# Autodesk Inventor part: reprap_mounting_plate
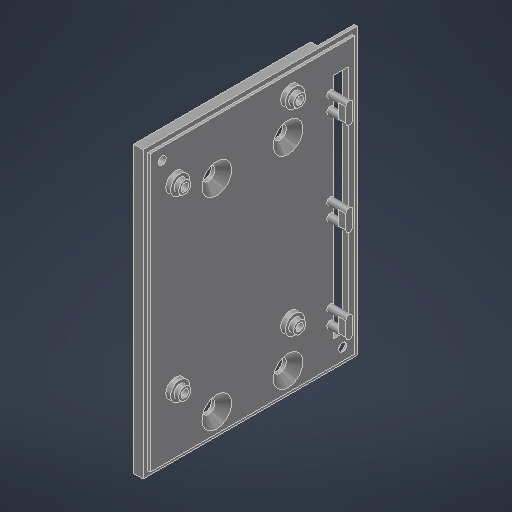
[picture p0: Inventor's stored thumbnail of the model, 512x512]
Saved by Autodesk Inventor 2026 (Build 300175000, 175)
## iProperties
Created: 2025-04
Part Number: reprap_mounting_plate
Material: 1.0037 S235JR
Document SubType Name: Modeling
Designer: BennF
Density: 7.85 g/cm^3
Appearance: Stahl
Author: BennF
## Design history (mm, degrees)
sketch "Sketch2"
  geometry: L1 (-45, 60)-(45, 60); L2 (45, 60)-(45, -60); L3 (45, -60)-(-45, -60); L4 (-45, -60)-(-45, 60); 3 further points
  constraints: 8 end point, 2 midpoint, 2 parallel, 1 horizontal, 1 horizontal alignment, 1 perpendicular, 1 vertical alignment
  dimensions: "d0" = 90 distance of L1.start L1.end; "d1" = 120 distance of L3.end L1.start
extrude "Extrusion1" new body sketch "Sketch2" distance "d2" = 5; taper "d3" = 0 deg
sketch "Sketch3"
  geometry: L1 (-60, 45)-(60, 45) reference; L2 (60, 45)-(-60, 45); L3 (-60, 45)-(-60, 29.5); L4 (-60, 29.5)-(60, 29.5); L5 (60, 29.5)-(60, 45); 2 further points
  constraints: 8 end point, 2 parallel, 1 horizontal, 1 perpendicular
  dimensions: "d4" = 29.5 distance from line of point (0, 0) L4
extrude "Extrusion2" cut sketch "Sketch3" distance "d5" = 2.8; taper "d6" = 0 deg
sketch "Sketch4"
  geometry: L1 (-35, -15)-(50, -15); L2 (50, -15)-(50, 15); L3 (50, 15)-(-35, 15); L4 (-35, 15)-(-35, -15); L5 (-60, 45)-(-60, -45) reference; L6 (60, -45)-(60, 45) reference; 4 further points
  constraints: 8 end point, 2 coincident, 2 parallel, 1 horizontal, 1 horizontal alignment, 1 midpoint, 1 perpendicular
  dimensions: "d14" = 30 distance of L3.end L1.start; "d31" = 25 distance between parallel lines of L4 L5; "d32" = 10 distance between parallel lines of L6 L2
hole "Hole1" sketch "Sketch4" at (-35, -15), (-35, 15), (50, -15), (50, 15) diameter "d7" = 5.5; stored, may be unused: countersink angle "d11" = 90 deg, drill point angle "d13" = 118 deg; dims "d8" = 6, "d9" = 12.5, "d10" = 3.4, "d12" = 8
sketch "Sketch5"
  geometry: L1 (32.626, -32.46)-(32.626, 15.876); L2 (-50, 15.876)-(32.626, 15.876); L3 (-60, 45)-(-60, -45) reference; L4 (60, 45)-(-60, 45) reference; L5 (-60, -45)-(60, -45) reference; C1 r 4 at (-42.507, -32.46); C2 r 4 at (-50, 15.876); C3 r 4 at (32.626, -32.46); C4 r 4 at (32.626, 15.876); 1 further point
  constraints: 4 centre point, 4 end point, 3 equal radius, 2 horizontal alignment, 1 horizontal, 1 vertical, 1 vertical alignment
  dimensions: "d16" = 48.336 distance of L1.start L1.end; "d17" = 75.133 distance of L1.start C1.centre; "d18" = 82.626 distance of L1.end L2.start; "d19" = 8 diameter of C1; "d29" = 10 distance from line of L3 L2.start; "d33" = 12.54 distance from line of L5 L1.start
extrude "Extrusion3" join sketch "Sketch5" distance "d20" = 4; taper "d21" = 0 deg
sketch "Sketch6"
  geometry: C1 r 4 at (50, 15.876) reference; C2 r 4 at (42.507, -32.46) reference; C3 r 4 at (-32.626, -32.46) reference; C4 r 4 at (-32.626, 15.876) reference; 5 further points
  constraints: 4 coincident
hole "Hole2" sketch "Sketch6" at (50, 15.876), (42.507, -32.46), (-32.626, 15.876), (-32.626, -32.46) diameter "d22" = 3.2; stored, may be unused: countersink angle "d26" = 90 deg, drill point angle "d28" = 118 deg; dims "d23" = 6, "d24" = 4, "d25" = 6.7, "d27" = 8
sketch "Sketch7"
  geometry: L1 (-48, 40.25)-(48, 40.25); L2 (48, 40.25)-(48, 34.25); L3 (48, 34.25)-(-48, 34.25); L4 (-48, 34.25)-(-48, 40.25); L5 (-60, 45)-(-60, 29.5) reference; 4 further points
  constraints: 8 end point, 3 midpoint, 2 parallel, 1 horizontal, 1 horizontal alignment, 1 perpendicular, 1 vertical alignment
  dimensions: "d34" = 6 distance of L3.end L1.start; "d37" = 12 distance between parallel lines of L5 L4
extrude "Extrusion4" cut sketch "Sketch7" stored distance "d35" = 3; taper "d36" = 0 deg
sketch "Sketch8"
  geometry: L1 (0, 4.5)-(8, 4.5); L2 (8, 4.5)-(8, 13.5); L3 (8, 13.5)-(0, 13.5); L4 (0, 7.5)-(5, 7.5); L5 (5, 7.5)-(5, 10.5); L6 (5, 10.5)-(0, 10.5); L7 (0, 43.5)-(8, 43.5); L8 (8, 43.5)-(8, 52.5); L9 (8, 52.5)-(0, 52.5); L10 (0, 49.5)-(5, 49.5); L11 (5, 49.5)-(5, 46.5); L12 (5, 46.5)-(0, 46.5); L13 (0, 85.5)-(5, 85.5); L14 (5, 85.5)-(5, 88.5); L15 (5, 88.5)-(0, 88.5); L16 (0, 82.5)-(8, 82.5); L17 (8, 82.5)-(8, 91.5); L18 (8, 91.5)-(0, 91.5); L19 (8, 82.5)-(8, 52.5); L20 (8, 43.5)-(8, 13.5); 9 further points
  constraints: 40 end point, 11 horizontal, 9 equal length, 7 perpendicular, 6 midpoint, 4 horizontal alignment, 1 collinear, 1 vertical, 13 other
  dimensions: "d38" = 8 distance of L1.start L1.end; "d39" = 3 distance of L4.end L5.end; "d40" = 3 distance between parallel lines of L1 L4; "d41" = 5 distance of L5.end L6.end; "d42" = 30 distance of L16.end L8.end
extrude "Extrusion5" join sketch "Sketch8" distance "d43" = 3; taper "d44" = 0 deg
fillet "Fillet1" dims "d45" = 1.5 (= 0.5 x d43)
sketch "Sketch9"
  geometry: L1 (-60, 45)-(-60, -45) reference; L2 (-60, -45)-(60, -45) reference; L3 (60, -45)-(60, 45) reference; L4 (60, 45)-(-60, 45) reference; L5 (-58, -43)-(-58, 43); L6 (-58, 43)-(58, 43); L7 (58, 43)-(58, -43); L8 (58, -43)-(-58, -43); 1 further point
  constraints: 8 end point, 3 other
  dimensions: "d46" = 2 distance between parallel lines of L1 L5
extrude "Extrusion6" cut sketch "Sketch9" distance "d47" = 1; taper "d48" = 0 deg
sketch "Sketch10"
  geometry: C1 r 4 at (0, 0) reference; C2 r 4 at (-7.493, 48.336) reference; C3 r 4 at (75.133, 0) reference; C4 r 4 at (75.133, 48.336) reference; C5 r 1.6 at (0, 0) reference; C6 r 1.6 at (-7.493, 48.336) reference; C7 r 1.6 at (75.133, 48.336) reference; C8 r 1.6 at (75.133, 0) reference; C9 r 2.6 at (0, 0); C10 r 2.6 at (-7.493, 48.336); C11 r 2.6 at (75.133, 0); C12 r 2.6 at (75.133, 48.336); 1 further point
  constraints: 4 centre point, 3 equal radius
  dimensions: "d49" = 1 radial gap between concentric circles of C5 C9
extrude "Extrusion7" cut sketch "Sketch10" distance "d50" = 2; taper "d51" = 0 deg
sketch "Sketch11"
  geometry: L1 (53, -38)-(60, -38); L2 (60, 29.5)-(60, -45) reference; L3 (53, -38)-(53, -45); L4 (60, -45)-(-60, -45) reference; 1 further point
  constraints: 4 end point, 2 point on line, 1 horizontal, 1 perpendicular, 1 vertical
  dimensions: "d59" = 7 distance of L1.start L1.end
hole "Hole3" sketch "Sketch11" at (53, -38) diameter "d52" = 3.4; stored, may be unused: countersink angle "d56" = 90 deg, drill point angle "d58" = 118 deg; dims "d53" = 6, "d54" = 7.5, "d55" = 2, "d57" = 8
sketch "Sketch12"
  geometry: L1 (-53, 38)-(-53, 45); L2 (60, 45)-(-60, 45) reference; L3 (-53, 38)-(-60, 38); L4 (-60, 29.5)-(-60, 45) reference; 1 further point
  constraints: 4 end point, 2 point on line, 1 horizontal, 1 perpendicular, 1 vertical
  dimensions: "d67" = 7 distance of L1.start L3.end (= d59)
hole "Hole4" sketch "Sketch12" at (-53, 38) diameter "d60" = 3.4; stored, may be unused: countersink angle "d64" = 90 deg, drill point angle "d66" = 118 deg; dims "d61" = 6, "d62" = 7.5, "d63" = 2, "d65" = 8
body "Solid1"
